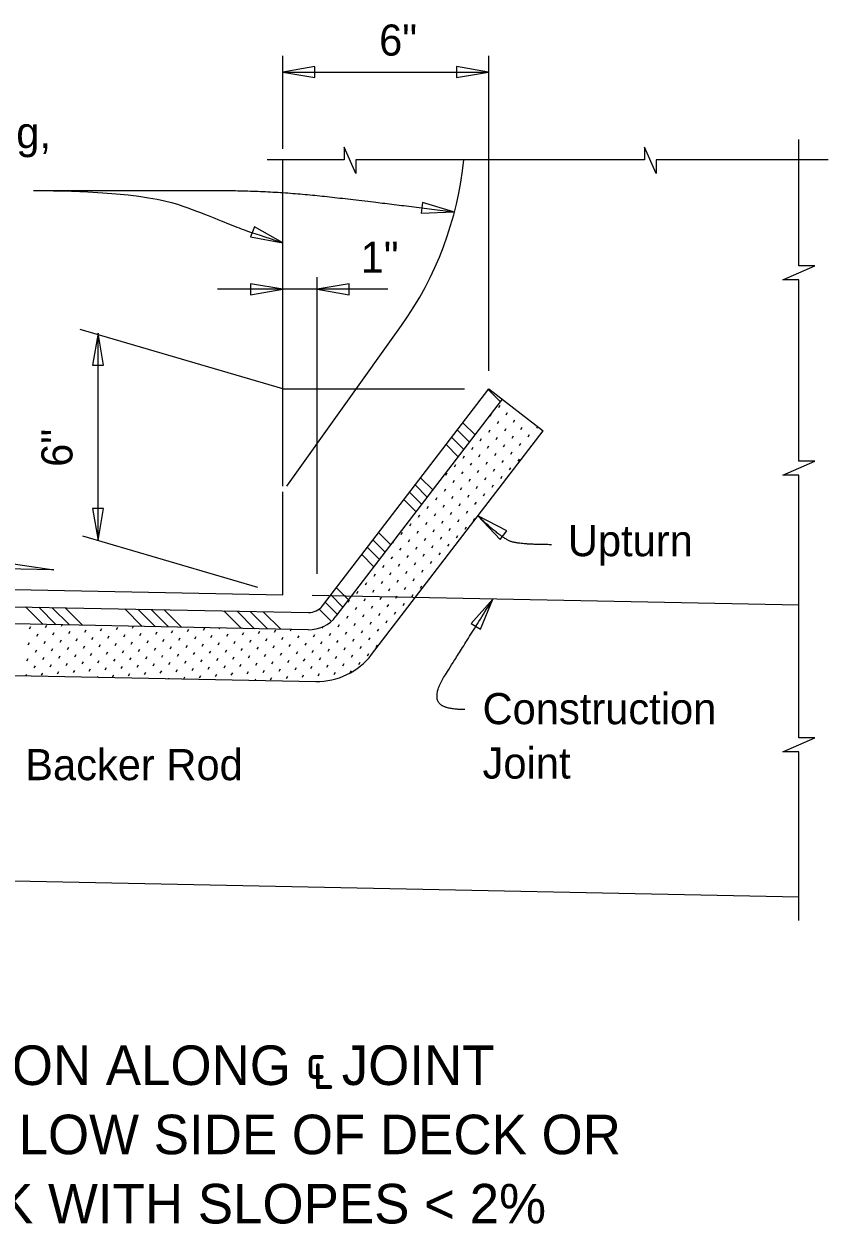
# Model space of a CAD drawing. Extents: x -7.9 to 27, y -3.1 to 14.6.
# Drawn here: x 11.283 to 13.235, y 11.645 to 14.558 of the extents above; entities that cross this region are included whole.
import ezdxf

# ---------------------------------------------------------------- set-up
doc = ezdxf.new("R2010")
doc.units = 0
for name, color, linetype in [('Border', 7, 'Continuous'), ('Patterning', 7, 'Continuous'), ('PlotBorder_dp', 7, 'Continuous'), ('SupstrConc_h', 7, 'Continuous'), ('TextMisc', 7, 'Continuous')]:
    doc.layers.add(name, color=color, linetype=linetype)

msp = doc.modelspace()

# ---------------------------------------------------------------- linework, layer by layer
at = {"layer": 'Patterning'}
for p, q in [((11.9108, 13.4356), (11.9108, 14.228)), ((11.9205, 13.4356), (12.199, 13.8255)), ((11.9107, 13.1719), (11.9107, 13.4219)), ((10.0289, 13.2096), (11.9108, 13.172)), ((13.1635, 12.4386), (9.8432, 12.5051))]:
    msp.add_line(p, q, dxfattribs=at)
msp.add_arc((11.521, 14.3099), 0.8333, 324.4623, 354.3636, dxfattribs=at)
at = {"layer": 'PlotBorder_dp'}
for p, q in [((11.9108, 14.2546), (11.9108, 14.4806)), ((12.4108, 13.7154), (12.4108, 14.4806)), ((11.9108, 14.4409), (12.4108, 14.4409)), ((11.9942, 13.2229), (11.9942, 13.9433)), ((12.1658, 13.9137), (11.7523, 13.9137)), ((11.9108, 13.672), (11.4193, 13.8164)), ((11.4625, 13.3037), (11.4625, 13.8075)), ((11.9108, 13.672), (12.3522, 13.672)), ((11.8504, 13.1897), (11.4258, 13.3145))]:
    msp.add_line(p, q, dxfattribs=at)
for points in [[(11.9108, 14.4409), (11.9889, 14.4277), (11.9889, 14.4541)], [(12.4107, 14.4409), (12.3326, 14.4541), (12.3326, 14.4277)], [(12.3257, 14.1014), (12.2499, 14.1245), (12.2465, 14.0983)], [(11.9108, 14.0261), (11.8421, 14.0655), (11.8329, 14.0407)], [(11.9108, 13.9136), (11.8327, 13.9269), (11.8327, 13.9004)], [(11.994, 13.9136), (12.0721, 13.9004), (12.0721, 13.9269)], [(11.4624, 13.8075), (11.4492, 13.7294), (11.4757, 13.7294)], [(11.4624, 13.3037), (11.4757, 13.3818), (11.4492, 13.3818)], [(12.3845, 13.3637), (12.4388, 13.306), (12.4547, 13.3271)], [(12.4212, 13.1618), (12.3684, 13.1027), (12.3908, 13.0886)]]:
    msp.add_lwpolyline(points, close=True, dxfattribs=at)
for points in [[(13.1635, 13.7261), (13.1635, 13.9366), (13.1247, 13.9366), (13.1635, 13.9535), (13.2022, 13.9704), (13.1635, 13.9704), (13.1635, 14.2775)], [(12.6016, 14.228), (12.0884, 14.228), (12.0884, 14.195), (12.0601, 14.2589), (12.0601, 14.228), (11.8726, 14.228)], [(13.2346, 14.228), (12.8174, 14.228), (12.8174, 14.195), (12.789, 14.2589), (12.789, 14.228), (12.6016, 14.228)], [(13.1635, 13.1859), (13.1635, 13.4629), (13.1247, 13.4629), (13.1635, 13.4798), (13.2022, 13.4966), (13.1635, 13.4966), (13.1635, 13.7261)], [(10.9147, 13.2405), (10.9512, 13.2929), (11.3547, 13.2329), (10.1512, 13.257)], [(13.1635, 12.3817), (13.1635, 12.7912), (13.1247, 12.7912), (13.1635, 12.8081), (13.2022, 12.825), (13.1635, 12.825), (13.1635, 13.1859)]]:
    msp.add_lwpolyline(points, dxfattribs=at)
for points, degree in [([(11.3058, 14.1535), (11.5753, 14.152), (11.7215, 14.0968), (11.821, 14.0545), (11.8641, 14.0427), (11.9108, 14.0261)], 3), ([(11.3058, 14.1535), (11.6231, 14.1535), (11.8818, 14.1535), (12.1349, 14.126), (12.3257, 14.1014)], 2), ([(12.5635, 13.2938), (12.4919, 13.2938), (12.4436, 13.3073), (12.3845, 13.3637)], 2), ([(12.3532, 12.8935), (12.2947, 12.8935), (12.2795, 12.9369), (12.3286, 13.0144), (12.4212, 13.1618)], 2)]:
    msp.add_open_spline(points, degree=degree, dxfattribs=at)
at = {"layer": 'SupstrConc_h'}
msp.add_line((13.1635, 13.1469), (11.9823, 13.1706), dxfattribs=at)
at = {"layer": 'TextMisc'}
for p, q in [((12.007, 13.1453), (12.4108, 13.6719)), ((12.4096, 13.6703), (12.4393, 13.6406)), ((12.4108, 13.6719), (12.5431, 13.5705)), ((12.4439, 13.6466), (12.0401, 13.1199)), ((12.4356, 13.6266), (12.4389, 13.6322)), ((12.4147, 13.6056), (12.4179, 13.6112)), ((12.4533, 13.6089), (12.4566, 13.6145)), ((12.3479, 13.5899), (12.3776, 13.5601)), ((12.4324, 13.5879), (12.4356, 13.5935)), ((12.4501, 13.5702), (12.4533, 13.5758)), ((12.4711, 13.5911), (12.4743, 13.5967)), ((12.4888, 13.5734), (12.492, 13.579)), ((12.5097, 13.5944), (12.5104, 13.5956)), ((12.5274, 13.5767), (12.5298, 13.5807)), ((12.1265, 13.0271), (12.5431, 13.5705)), ((12.3208, 13.5545), (12.3505, 13.5248)), ((12.3343, 13.5722), (12.3641, 13.5425)), ((12.3905, 13.546), (12.3937, 13.5516)), ((12.4114, 13.5669), (12.4147, 13.5725)), ((12.4291, 13.5492), (12.4324, 13.5548)), ((12.4678, 13.5525), (12.4711, 13.5581)), ((12.5065, 13.5557), (12.5097, 13.5613)), ((12.3072, 13.5369), (12.337, 13.5071)), ((12.3695, 13.525), (12.3728, 13.5306)), ((12.4082, 13.5283), (12.4114, 13.5339)), ((12.4259, 13.5106), (12.4291, 13.5162)), ((12.4469, 13.5315), (12.4501, 13.5371)), ((12.4646, 13.5138), (12.4678, 13.5194)), ((12.4855, 13.5348), (12.4888, 13.5404)), ((12.3276, 13.4831), (12.3309, 13.4887)), ((12.3486, 13.5041), (12.3518, 13.5097)), ((12.3663, 13.4864), (12.3695, 13.492)), ((12.3872, 13.5073), (12.3905, 13.5129)), ((12.405, 13.4896), (12.4082, 13.4952)), ((12.4436, 13.4929), (12.4469, 13.4984)), ((12.4823, 13.4961), (12.4855, 13.5017)), ((12.2455, 13.4564), (12.2753, 13.4267)), ((12.3067, 13.4622), (12.3099, 13.4678)), ((12.3453, 13.4654), (12.3486, 13.471)), ((12.384, 13.4687), (12.3872, 13.4743)), ((12.4017, 13.4509), (12.405, 13.4565)), ((12.4227, 13.4719), (12.4259, 13.4775)), ((12.4404, 13.4542), (12.4436, 13.4598)), ((12.4613, 13.4751), (12.4646, 13.4807)), ((12.232, 13.4388), (12.2617, 13.409)), ((12.3034, 13.4235), (12.3067, 13.4291)), ((12.3244, 13.4445), (12.3276, 13.4501)), ((12.3421, 13.4267), (12.3453, 13.4323)), ((12.363, 13.4477), (12.3663, 13.4533)), ((12.3808, 13.43), (12.384, 13.4356)), ((12.4194, 13.4332), (12.4227, 13.4388)), ((12.2049, 13.4034), (12.2347, 13.3737)), ((12.2185, 13.4211), (12.2482, 13.3914)), ((12.2825, 13.4025), (12.2857, 13.4081)), ((12.3211, 13.4058), (12.3244, 13.4114)), ((12.3598, 13.409), (12.363, 13.4146)), ((12.3985, 13.4123), (12.4017, 13.4179)), ((12.2615, 13.3816), (12.2647, 13.3872)), ((12.2792, 13.3639), (12.2825, 13.3695)), ((12.3002, 13.3848), (12.3034, 13.3904)), ((12.3179, 13.3671), (12.3211, 13.3727)), ((12.3388, 13.3881), (12.3421, 13.3937)), ((12.3566, 13.3704), (12.3598, 13.376)), ((12.3775, 13.3913), (12.3808, 13.3969)), ((12.2196, 13.3397), (12.2228, 13.3453)), ((12.2405, 13.3606), (12.2438, 13.3662)), ((12.2583, 13.3429), (12.2615, 13.3485)), ((12.2969, 13.3462), (12.3002, 13.3518)), ((12.3356, 13.3494), (12.3388, 13.355)), ((12.3743, 13.3526), (12.3775, 13.3582)), ((12.1432, 13.323), (12.173, 13.2932)), ((12.1986, 13.3187), (12.2019, 13.3243)), ((12.2373, 13.322), (12.2405, 13.3276)), ((12.276, 13.3252), (12.2792, 13.3308)), ((12.2937, 13.3075), (12.2969, 13.3131)), ((12.3146, 13.3284), (12.3179, 13.334)), ((12.3324, 13.3107), (12.3356, 13.3163)), ((12.3533, 13.3317), (12.3566, 13.3373)), ((12.1161, 13.2876), (12.1459, 13.2579)), ((12.1297, 13.3053), (12.1594, 13.2756)), ((12.1777, 13.2978), (12.1809, 13.3034)), ((12.1954, 13.2801), (12.1986, 13.2857)), ((12.2164, 13.301), (12.2196, 13.3066)), ((12.2341, 13.2833), (12.2373, 13.2889)), ((12.255, 13.3043), (12.2583, 13.3098)), ((12.2727, 13.2865), (12.276, 13.2921)), ((12.3114, 13.2898), (12.3146, 13.2954)), ((12.1026, 13.27), (12.1323, 13.2402)), ((12.1744, 13.2591), (12.1777, 13.2647)), ((12.2131, 13.2623), (12.2164, 13.2679)), ((12.2518, 13.2656), (12.255, 13.2712)), ((12.2695, 13.2479), (12.2727, 13.2535)), ((12.2905, 13.2688), (12.2937, 13.2744)), ((12.1535, 13.2381), (12.1567, 13.2437)), ((12.1712, 13.2204), (12.1744, 13.226)), ((12.1922, 13.2414), (12.1954, 13.247)), ((12.2099, 13.2237), (12.2131, 13.2293)), ((12.2308, 13.2446), (12.2341, 13.2502)), ((12.2485, 13.2269), (12.2518, 13.2325)), ((12.1116, 13.1962), (12.1148, 13.2018)), ((12.1325, 13.2172), (12.1358, 13.2228)), ((12.1502, 13.1995), (12.1535, 13.2051)), ((12.1889, 13.2027), (12.1922, 13.2083)), ((12.2276, 13.206), (12.2308, 13.2116)), ((12.2669, 13.2102), (12.2695, 13.2148)), ((9.8432, 13.1716), (11.9731, 13.129)), ((12.0274, 13.1718), (12.0571, 13.1421)), ((12.0409, 13.1895), (12.0706, 13.1598)), ((12.0906, 13.1753), (12.0939, 13.1809)), ((12.1293, 13.1785), (12.1325, 13.1841)), ((12.147, 13.1608), (12.1502, 13.1664)), ((12.168, 13.1818), (12.1712, 13.1874)), ((12.1857, 13.164), (12.1889, 13.1696)), ((12.2066, 13.185), (12.2099, 13.1906)), ((12.2243, 13.1673), (12.2276, 13.1729)), ((12.2453, 13.1882), (12.2485, 13.1938)), ((11.2867, 13.1427), (11.3293, 13.1002)), ((11.3186, 13.1421), (11.3611, 13.0995)), ((11.3504, 13.1415), (11.393, 13.0989)), ((11.3823, 13.1408), (11.4248, 13.0983)), ((11.5273, 13.1379), (11.5699, 13.0954)), ((11.5592, 13.1373), (11.6017, 13.0947)), ((11.591, 13.1366), (11.6336, 13.0941)), ((11.6228, 13.136), (11.6654, 13.0934)), ((11.9988, 13.138), (12.0277, 13.1091)), ((12.0138, 13.1542), (12.0436, 13.1244)), ((12.0697, 13.1543), (12.0729, 13.1599)), ((12.0874, 13.1366), (12.0906, 13.1422)), ((12.1083, 13.1576), (12.1116, 13.1632)), ((12.126, 13.1398), (12.1293, 13.1454)), ((12.1647, 13.1431), (12.168, 13.1487)), ((12.2034, 13.1463), (12.2066, 13.1519)), ((11.9723, 13.0873), (9.8432, 13.1299)), ((11.7679, 13.1331), (11.8105, 13.0905)), ((11.7998, 13.1325), (11.8423, 13.0899)), ((11.8316, 13.1318), (11.8742, 13.0893)), ((11.8634, 13.1312), (11.906, 13.0886)), ((12.0664, 13.1157), (12.0697, 13.1213)), ((12.1051, 13.1189), (12.1083, 13.1245)), ((12.1228, 13.1012), (12.126, 13.1068)), ((12.1438, 13.1221), (12.147, 13.1277)), ((12.1615, 13.1044), (12.1647, 13.11)), ((12.1824, 13.1254), (12.1857, 13.131)), ((11.2963, 13.0895), (11.2995, 13.0951)), ((11.3349, 13.0927), (11.3382, 13.0983)), ((11.3527, 13.075), (11.3559, 13.0806)), ((11.3736, 13.096), (11.3755, 13.0992)), ((11.3913, 13.0783), (11.3946, 13.0839)), ((11.43, 13.0815), (11.4332, 13.0871)), ((11.4687, 13.0848), (11.4719, 13.0904)), ((11.5073, 13.088), (11.5106, 13.0936)), ((11.546, 13.0912), (11.5486, 13.0958)), ((11.5637, 13.0735), (11.567, 13.0791)), ((11.5847, 13.0945), (11.585, 13.0951)), ((11.6024, 13.0768), (11.6056, 13.0824)), ((11.6411, 13.08), (11.6443, 13.0856)), ((11.6797, 13.0832), (11.683, 13.0888)), ((11.7184, 13.0865), (11.7216, 13.0921)), ((11.7571, 13.0897), (11.7581, 13.0916)), ((11.7748, 13.072), (11.778, 13.0776)), ((11.8134, 13.0753), (11.8167, 13.0808)), ((11.8521, 13.0785), (11.8554, 13.0841)), ((11.8908, 13.0817), (11.894, 13.0873)), ((11.9295, 13.085), (11.9313, 13.0881)), ((12.0068, 13.0915), (12.0088, 13.095)), ((12.0245, 13.0737), (12.0278, 13.0793)), ((12.0455, 13.0947), (12.0487, 13.1003)), ((12.0632, 13.077), (12.0664, 13.0826)), ((12.0841, 13.0979), (12.0874, 13.1035)), ((12.1019, 13.0802), (12.1051, 13.0858)), ((12.1405, 13.0835), (12.1438, 13.0891)), ((11.293, 13.0508), (11.2963, 13.0564)), ((11.314, 13.0718), (11.3172, 13.0774)), ((11.3317, 13.0541), (11.3349, 13.0597)), ((11.3704, 13.0573), (11.3736, 13.0629)), ((11.409, 13.0606), (11.4123, 13.0662)), ((11.4268, 13.0428), (11.43, 13.0484)), ((11.4477, 13.0638), (11.4509, 13.0694)), ((11.4654, 13.0461), (11.4687, 13.0517)), ((11.4864, 13.067), (11.4896, 13.0726)), ((11.5041, 13.0493), (11.5073, 13.0549)), ((11.525, 13.0703), (11.5283, 13.0759)), ((11.5428, 13.0526), (11.546, 13.0582)), ((11.5814, 13.0558), (11.5847, 13.0614)), ((11.6201, 13.059), (11.6233, 13.0646)), ((11.6588, 13.0623), (11.662, 13.0679)), ((11.6765, 13.0446), (11.6797, 13.0502)), ((11.6974, 13.0655), (11.7007, 13.0711)), ((11.7152, 13.0478), (11.7184, 13.0534)), ((11.7361, 13.0688), (11.7394, 13.0744)), ((11.7538, 13.0511), (11.7571, 13.0567)), ((11.7925, 13.0543), (11.7957, 13.0599)), ((11.8312, 13.0575), (11.8344, 13.0631)), ((11.8698, 13.0608), (11.8731, 13.0664)), ((11.8875, 13.0431), (11.8908, 13.0487)), ((11.9085, 13.064), (11.9117, 13.0696)), ((11.9262, 13.0463), (11.9295, 13.0519)), ((11.9472, 13.0673), (11.9504, 13.0729)), ((11.9649, 13.0495), (11.9681, 13.0551)), ((11.9858, 13.0705), (11.9891, 13.0761)), ((12.0036, 13.0528), (12.0068, 13.0584)), ((12.0422, 13.056), (12.0455, 13.0616)), ((12.0809, 13.0593), (12.0841, 13.0649)), ((12.1196, 13.0625), (12.1228, 13.0681)), ((12.1373, 13.0448), (12.1405, 13.0504)), ((11.3107, 13.0331), (11.314, 13.0387)), ((11.3285, 13.0154), (11.3317, 13.021)), ((11.3494, 13.0364), (11.3527, 13.042)), ((11.3671, 13.0186), (11.3704, 13.0242)), ((11.3881, 13.0396), (11.3913, 13.0452)), ((11.4058, 13.0219), (11.409, 13.0275)), ((11.4445, 13.0251), (11.4477, 13.0307)), ((11.4831, 13.0284), (11.4864, 13.034)), ((11.5218, 13.0316), (11.525, 13.0372)), ((11.5395, 13.0139), (11.5428, 13.0195)), ((11.5605, 13.0349), (11.5637, 13.0404)), ((11.5782, 13.0171), (11.5814, 13.0227)), ((11.5991, 13.0381), (11.6024, 13.0437)), ((11.6169, 13.0204), (11.6201, 13.026)), ((11.6378, 13.0413), (11.6411, 13.0469)), ((11.6555, 13.0236), (11.6588, 13.0292)), ((11.6942, 13.0269), (11.6974, 13.0325)), ((11.7329, 13.0301), (11.7361, 13.0357)), ((11.7715, 13.0333), (11.7748, 13.0389)), ((11.7893, 13.0156), (11.7925, 13.0212)), ((11.8102, 13.0366), (11.8134, 13.0422)), ((11.8279, 13.0189), (11.8312, 13.0245)), ((11.8489, 13.0398), (11.8521, 13.0454)), ((11.8666, 13.0221), (11.8698, 13.0277)), ((11.9053, 13.0253), (11.9085, 13.0309)), ((11.9439, 13.0286), (11.9472, 13.0342)), ((11.9826, 13.0318), (11.9858, 13.0374)), ((12.0003, 13.0141), (12.0036, 13.0197)), ((12.0213, 13.0351), (12.0245, 13.0407)), ((12.039, 13.0174), (12.0422, 13.023)), ((12.0599, 13.0383), (12.0632, 13.0439)), ((12.0777, 13.0206), (12.0809, 13.0262)), ((12.0986, 13.0416), (12.1019, 13.0472)), ((12.1163, 13.0238), (12.1196, 13.0294)), ((9.8432, 13.0049), (11.9908, 12.9619)), ((11.2898, 13.0122), (11.293, 13.0178)), ((11.3075, 12.9945), (11.3107, 13)), ((11.3462, 12.9977), (11.3494, 13.0033)), ((11.3848, 13.0009), (11.3881, 13.0065)), ((11.4235, 13.0042), (11.4268, 13.0098)), ((11.4412, 12.9865), (11.4445, 12.9921)), ((11.4622, 13.0074), (11.4654, 13.013)), ((11.4799, 12.9897), (11.4831, 12.9953)), ((11.5008, 13.0107), (11.5041, 13.0163)), ((11.5186, 12.9929), (11.5218, 12.9985)), ((11.5572, 12.9962), (11.5605, 13.0018)), ((11.5959, 12.9994), (11.5991, 13.005)), ((11.6346, 13.0027), (11.6378, 13.0083)), ((11.6523, 12.9849), (11.6555, 12.9905)), ((11.6732, 13.0059), (11.6765, 13.0115)), ((11.691, 12.9882), (11.6942, 12.9938)), ((11.7119, 13.0091), (11.7152, 13.0147)), ((11.7296, 12.9914), (11.7329, 12.997)), ((11.7506, 13.0124), (11.7538, 13.018)), ((11.7683, 12.9947), (11.7715, 13.0003)), ((11.807, 12.9979), (11.8102, 13.0035)), ((11.8456, 13.0012), (11.8489, 13.0068)), ((11.8843, 13.0044), (11.8875, 13.01)), ((11.902, 12.9867), (11.9053, 12.9923)), ((11.923, 13.0076), (11.9262, 13.0132)), ((11.9407, 12.9899), (11.9439, 12.9955)), ((11.9616, 13.0109), (11.9649, 13.0165)), ((11.9794, 12.9932), (11.9826, 12.9988)), ((12.018, 12.9964), (12.0213, 13.002)), ((12.0567, 12.9996), (12.0599, 13.0052)), ((12.0954, 13.0029), (12.0986, 13.0085)), ((11.288, 12.976), (11.2898, 12.9791)), ((11.3252, 12.9767), (11.3285, 12.9823)), ((11.3639, 12.98), (11.3671, 12.9856)), ((11.4026, 12.9832), (11.4058, 12.9888)), ((11.4611, 12.9725), (11.4622, 12.9743)), ((11.4976, 12.972), (11.5008, 12.9776)), ((11.5363, 12.9752), (11.5395, 12.9808)), ((11.5749, 12.9785), (11.5782, 12.9841)), ((11.6136, 12.9817), (11.6169, 12.9873)), ((11.6343, 12.969), (11.6346, 12.9696)), ((11.6706, 12.9683), (11.6732, 12.9728)), ((11.7087, 12.9705), (11.7119, 12.9761)), ((11.7473, 12.9737), (11.7506, 12.9793)), ((11.786, 12.977), (11.7893, 12.9826)), ((11.8247, 12.9802), (11.8279, 12.9858)), ((11.8438, 12.9649), (11.8456, 12.9681)), ((11.8634, 12.9834), (11.8666, 12.989)), ((11.8811, 12.9657), (11.8843, 12.9713)), ((11.9197, 12.969), (11.923, 12.9746)), ((11.9584, 12.9722), (11.9616, 12.9778)), ((11.9971, 12.9754), (12.0003, 12.981)), ((12.0357, 12.9787), (12.039, 12.9843)), ((12.0749, 12.9828), (12.0777, 12.9875))]:
    msp.add_line(p, q, dxfattribs=at)
for centre, radius in [((11.9739, 13.1707), 0.0417), ((11.974, 13.1706), 0.0833), ((11.9942, 13.1286), 0.1667)]:
    msp.add_arc(centre, radius, 268.8533, 322.5215, dxfattribs=at)

# ---------------------------------------------------------------- texts
at = {"layer": 'Border'}
for s, p in [('6"', (12.1448, 14.4808)), ('1"', (12.1, 13.9537)), ('Upturn', (12.603, 13.2658)), ('Foam Backer Rod', (10.9991, 12.7222))]:
    msp.add_text(s, height=0.0756, dxfattribs=at).set_placement(p)
msp.add_text('6"', height=0.0756, rotation=90, dxfattribs=at).set_placement((11.4004, 13.4827))
at = {"layer": 'PlotBorder_dp'}
for s, height, p in [('Face of Traffic Railing, ', 0.0756, (10.3369, 14.2563)), ('Construction ', 0.0756, (12.3959, 12.8581)), ('Joint', 0.0756, (12.3959, 12.7261)), ('PARTIAL SECTION ALONG ℄ JOINT', 0.096, (10.3042, 11.9823)), ('JOINT TREATMENT AT LOW SIDE OF DECK OR', 0.096, (9.8432, 11.8143)), ('HIGH SIDE OF DECK WITH SLOPES < 2%', 0.096, (10.0428, 11.6463))]:
    msp.add_text(s, height=height, dxfattribs=at).set_placement(p)

doc.saveas('drawing.dxf')
